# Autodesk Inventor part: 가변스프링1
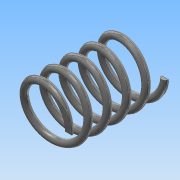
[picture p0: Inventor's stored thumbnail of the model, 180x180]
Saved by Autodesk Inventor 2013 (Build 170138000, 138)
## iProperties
Created: 2018-10
Part Number: 가변스프링1
Material: 스테인리스강
Document SubType Name: Modeling
Designer: Administrator
Density: 8.08 g/cm^3
Mass: 6.29078 g
Surface Area: 15.7849 cm^2
Volume: 0.778561 cm^3
Author: Administrator
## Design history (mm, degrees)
sketch "스케치1"
  geometry: L1 (0, 0)-(0, 28.698); L2 (0, 0)-(8, 0); L3 (0, 28.698)-(8, 28.698); C1 r 1 at (8, 0); 1 further point
  constraints: 6 end point, 2 coincident, 1 centre point, 1 parallel, 1 perpendicular, 1 vertical
  dimensions: "d0" = 28.6978 distance of L1.start L1.end (derived); "d1" = 8 distance of L1.start L2.end; "d2" = 2 diameter of C1; "d3" = 8 distance of L1.end L3.end
feature "코일1" sketch "스케치1" pitch "d4" = 10; turns "d6" = 5; dims "d5" = 28.6978 (= d0), "d7" = 0, angle "d8" = 90 deg, angle "d9" = 90 deg, "d10" = 0, "d11" = 0
sketch "스케치2"
  geometry: L1 (0, -10)-(28.698, -10); L2 (28.698, -10)-(28.698, 10); L3 (28.698, 10)-(0, 10); L4 (0, 10)-(0, -10); 2 further points
  constraints: 8 end point, 2 parallel, 1 coincident, 1 horizontal, 1 midpoint, 1 perpendicular
  dimensions: "d12" = 20 distance of L3.end L1.start; "d14" = 28.6978 distance of L1.start L1.end (derived)
extrude "돌출1" sketch "스케치2" stored distance "d15" = 0; taper "d16" = 0 deg
node "솔리드1"
